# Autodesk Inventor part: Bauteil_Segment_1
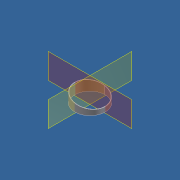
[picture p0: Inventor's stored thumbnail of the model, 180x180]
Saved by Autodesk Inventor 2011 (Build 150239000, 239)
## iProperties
Created: 2009-03
Part Number: Bauteil_Segment_1
Material: S235JR
Document SubType Name: Blech
Designer: Guido Walteich
Density: 7.86 g/cm^3
Flat Pattern Width: 4.7739 cm
Flat Pattern Length: 49.112 cm
Flat Pattern Area: 234.456 cm^2
Mass: 369.411 g
Surface Area: 345.06 cm^2
Volume: 46.9989 cm^3
Description: Blech
Sheet Metal Rule: Standard_mm
Stärke: 3 mm
d0: 160 mm
d6: 48 mm
Gestr_Neutral: 491 mm
Maße: = Ø<d0> x L=<d6> , aus Blech <Stärke> x <d6> x <Gestr_neutral>
Author: Guido Walteich
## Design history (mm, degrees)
node "Skizze1"
node "Konturlasche1"
  sketch "Skizze2"
    geometry: L1 (-98, 0)-(98, 0) reference; L2 (0, -98.1)-(0, 98.6) reference; A1 r 80 centre (0, 0) between (-0.5, 79.998) and (0.5, 79.998); A2 r 0.5 centre (0, 80) between (0.5, 79.998) and (-0.5, 79.998)
    constraints: 5 point on circle, 2 centre point, 2 point on line, 1 midpoint
    dimensions: "d0" = 160 diameter of A1 (= Rohr_D); "d1" = 1 diameter of A2
workplane "Arbeitsebene1"
workplane "Arbeitsebene2"
sketch "Skizze5"
  geometry: L1 (-80, 47.739)-(80, 47.739) reference; L2 (80, 0)-(80, 47.739) reference; L3 (-80, 0)-(-80, 47.739) reference; L4 (80, 0)-(-80, 0) reference; L5 (80, 47.739)-(-80, 15.913); 4 further points
  constraints: 2 end point, 1 point on line
  dimensions: "d18" = 11.25 deg angle of L1 L5 (= WINKEL)
extrude "Extrusion1" cut sketch "Skizze5" stored distance "d19" = 320 (= 2 x Rohr_D); taper "d20" = 0 deg
node "Volumenkörper1"
feature "Grobblech1" dims "d2" = 3 (= BreiteBiegungsfreistellung), "d3" = 1.5 (= TiefeBiegungsfreistellung), "d4" = 6 (= MinimalRest), "d5" = 3 (= Biegeradius), "d6" = 47.73896 (= Länge_1), "d7" = 3 (= Biegeradius), "d8" = 3 (= Wandstärke), "d9" = 12 (= GrößeEckenfreistellung), "d10" = 3 (= Stärke), "d11" = 3 (= JacobiRadiusGröße), "Stärke" = 3 (= Wandstärke), "AbstandVerbindung" = 0.01
feature "Biegung1" dims "d2" = 3 (= BreiteBiegungsfreistellung), "d3" = 1.5 (= TiefeBiegungsfreistellung), "d4" = 6 (= MinimalRest), "d5" = 3 (= Biegeradius), "d7" = 3 (= Biegeradius), "d8" = 3 (= Wandstärke), "Stärke" = 3 (= Wandstärke), "AbstandVerbindung" = 0.01
feature "Ecke1" dims "d8" = 3 (= Wandstärke), "d9" = 12 (= GrößeEckenfreistellung), "d10" = 3 (= Stärke), "d11" = 3 (= JacobiRadiusGröße)
feature "Definition1"
other parameters: "KFaktor" = 4.4, "Biegeradius" = 3 (= Stärke), "BreiteBiegungsfreistellung" = 3 (= Stärke), "TiefeBiegungsfreistellung" = 1.5 (= 0.5 x Stärke), "GrößeEckenfreistellung" = 12 (= 4 x Stärke), "MinimalRest" = 6 (= 2 x Stärke), "Übergangsradius" = 3 (= Biegeradius), "JacobiRadiusGröße" = 3 (= Biegeradius), "Rohr_D" = 160 [user parameter; used in 3 equation terms], "WINKEL_1" = 1.9635 [user parameter], "Länge_1" = 47.73896 [user parameter; used in 1 equation term], "Wandstärke" = 3 [user parameter; used in 3 equation terms], "d12" = 0, "d13" = 0, "Gestr_Neutral" = 490.87375 (computed from Rohr_D, Wandstärke) [user parameter], "WINKEL" = 11.25 deg [user parameter; used in 1 equation term], "Länge_2" = 95.47792 [user parameter], "Länge_3" = 95.47792 [user parameter], "Länge_4" = 95.47792 [user parameter], "Länge_5" = 47.73896 [user parameter], "ANZ_TEILE" = 39.78874 [user parameter], "GES_WINKEL" = 90 deg [user parameter], "Abstandsgröße" = 3 (= Stärke), "Länge_1" = 47.73896, "WINKEL_1" = 1.9635, "Wandstärke" = 3, "Biegeradius" = 3, "BreiteBiegungsfreistellung" = 3, "GrößeEckenfreistellung" = 12, "JacobiRadiusGröße" = 3, "MinimalRest" = 6, "Stärke" = 3, "TiefeBiegungsfreistellung" = 1.5, "Übergangsradius" = 3, "Gestr_Neutral" = 490.87375, "Länge_2" = 95.47792, "Länge_3" = 95.47792, "Länge_4" = 95.47792, "Länge_5" = 47.73896, "WINKEL" = 1.9635, "ANZ_TEILE" = 39.78874, "GES_WINKEL" = 90 deg, "Abstandsgröße" = 3
